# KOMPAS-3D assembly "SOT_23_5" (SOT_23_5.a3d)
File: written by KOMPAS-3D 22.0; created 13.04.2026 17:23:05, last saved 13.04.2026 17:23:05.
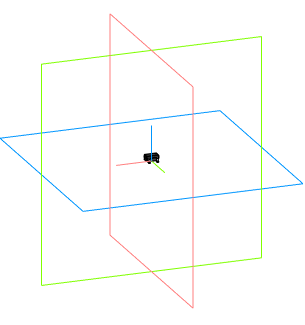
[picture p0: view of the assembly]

Document properties: Автор: Andrey; Полное имя файла: C:\Users\User1\Documents\SOT_23_5.a3d

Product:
- Component [detail]: DBV5A  | qty 1  | source file: DBV5A.m3d
- Part/product: SOT_23_5
    Комментарий: SOT_23_5

Referenced files in C:\Users\User1\Documents\: DBV5A.m3d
